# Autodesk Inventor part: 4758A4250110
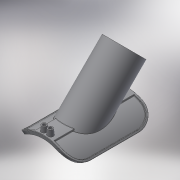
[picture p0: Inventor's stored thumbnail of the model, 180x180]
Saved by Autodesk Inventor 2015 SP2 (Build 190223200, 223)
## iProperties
Created: 2017-08
Part Number: 4758A4250110
Material: Generic
Description: PLASSON WASTE WATER SADDLE 45 INLET 225-315 X 110
Document SubType Name: Modeling
Designer: Кирилл
Density: 1 g/cm^3
Appearance: Default
Author: Кирилл
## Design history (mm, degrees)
derived "4758A4.ipt"
feature "Solid1::4758A4.ipt"
feature "Solid2::4758A4.ipt"
tag "TaggingFeature1"
body "Solid1"
other parameters: "d0" = 315, "d1" = 221, "d2" = 340.2, "d3" = 255, "d4" = 0, "d5" = 66.3, "d6" = 9.45, "d7" = 30 deg, "d8" = 15 deg, "d10" = 0, "d11" = 204.75, "d12" = 15, "d13" = 15, "d14" = 114.75, "d18" = 5 deg, "d19" = 4, "d20" = 4, "d23" = 14, "d24" = 0, "d25" = 4, "d26" = 0, "d27" = 45 deg, "d30" = 158, "d32" = 93.5, "d35" = 0, "d37" = 0, "d38" = 1.575, "d39" = 3.15, "d40" = 183.5, "d41" = 15, "d42" = 114.75, "d43" = 18.7, "d44" = 9.35, "d46" = 5 deg, "d47" = 4, "d49" = 4, "d51" = 14, "d52" = 0, "d53" = 3, "d54" = 0, "d_" = 315, "B_" = 221, "H_" = 158, "L_" = 255
